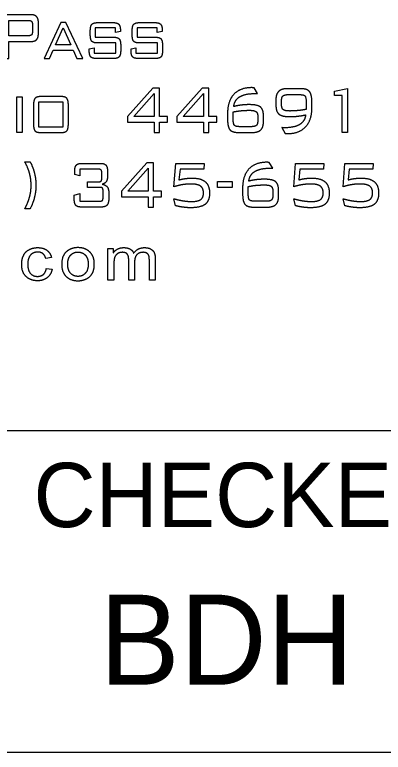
# Model space of a CAD drawing. Extents: x 0 to 34, y 0 to 22.
# Drawn here: x 32.806 to 33.379, y 2.5 to 3.647 of the extents above; entities that cross this region are included whole.
import ezdxf

# ---------------------------------------------------------------- set-up
doc = ezdxf.new("R2010")
doc.units = 0
for name, color, linetype in [('SH_Border', 7, 'Continuous'), ('SH_Data', 7, 'Continuous'), ('TX_X_20', 7, 'Continuous')]:
    doc.layers.add(name, color=color, linetype=linetype)

msp = doc.modelspace()

# ---------------------------------------------------------------- linework, layer by layer
at = {"layer": 'SH_Border'}
for p, q in [((32, 3), (33.5, 3)), ((32, 2.5), (33.5, 2.5))]:
    msp.add_line(p, q, dxfattribs=at)
at = {"layer": 'TX_X_20'}
for p, q in [((32.8336, 3.6306), (32.8336, 3.6211)), ((32.8429, 3.6181), (32.8429, 3.6334)), ((32.9344, 3.6343), (32.9593, 3.6343)), ((32.9994, 3.6343), (33.0243, 3.6343)), ((32.9235, 3.6158), (32.9235, 3.6211)), ((32.9886, 3.6158), (32.9886, 3.6211)), ((32.9708, 3.5984), (32.9708, 3.5917)), ((33.0358, 3.5984), (33.0358, 3.5917)), ((32.9599, 3.5785), (32.9327, 3.5785)), ((33.025, 3.5785), (32.9977, 3.5785)), ((33.1837, 3.524), (33.1782, 3.5329)), ((33.2512, 3.5315), (33.2296, 3.5315)), ((33.2314, 3.5224), (33.248, 3.5224)), ((32.8784, 3.5193), (32.8461, 3.5193)), ((33.2121, 3.5149), (33.2121, 3.5057)), ((33.2208, 3.5075), (33.2208, 3.5119)), ((33.268, 3.5016), (33.268, 3.5105)), ((32.8352, 3.506), (32.8352, 3.4767)), ((32.8894, 3.4767), (32.8894, 3.506)), ((33.259, 3.4994), (33.259, 3.4994)), ((33.1369, 3.4934), (33.1369, 3.4844)), ((33.1457, 3.4955), (33.1457, 3.4955)), ((33.184, 3.4874), (33.184, 3.4831)), ((33.1927, 3.48), (33.1927, 3.4892)), ((32.8461, 3.4635), (32.8784, 3.4635)), ((33.1536, 3.4635), (33.1752, 3.4635)), ((33.1734, 3.4725), (33.1569, 3.4725)), ((33.2211, 3.4711), (33.2266, 3.462)), ((32.8215, 3.4181), (32.8299, 3.4181)), ((33.2072, 3.408), (33.2016, 3.4169)), ((32.9109, 3.4155), (32.9386, 3.4155)), ((32.9415, 3.3947), (32.9415, 3.3987)), ((32.9503, 3.4022), (32.9503, 3.396)), ((32.9434, 3.3629), (32.9434, 3.372)), ((33.1603, 3.3774), (33.1603, 3.3684)), ((33.1692, 3.3795), (33.1692, 3.3795)), ((33.2074, 3.3715), (33.2074, 3.3671)), ((33.2162, 3.364), (33.2162, 3.3733)), ((32.9523, 3.3692), (32.9523, 3.362)), ((33.0561, 3.3496), (33.0535, 3.3605)), ((33.2423, 3.3496), (33.2397, 3.3605)), ((33.3191, 3.3496), (33.3165, 3.3605)), ((33.1969, 3.3565), (33.1803, 3.3565)), ((32.8299, 3.3448), (32.8215, 3.3448)), ((32.9399, 3.3475), (32.9102, 3.3475)), ((33.1771, 3.3475), (33.1987, 3.3475)), ((32.8632, 3.2689), (32.8543, 3.2676)), ((32.879, 3.2587), (32.879, 3.2587)), ((32.8884, 3.2587), (32.8884, 3.2587)), ((32.8551, 3.2521), (32.8641, 3.251))]:
    msp.add_line(p, q, dxfattribs=at)
for points in [[(32.8313, 3.6465), (32.7875, 3.6465), (32.7875, 3.5785), (32.7966, 3.5785), (32.7966, 3.605), (32.8313, 3.605)], [(32.8278, 3.6139), (32.7966, 3.6139), (32.7966, 3.6377), (32.8278, 3.6377)], [(32.9703, 3.6221), (32.9703, 3.6207), (32.9626, 3.6187), (32.9626, 3.626), (32.9312, 3.626), (32.9312, 3.6116), (32.9599, 3.6116)], [(33.0353, 3.6221), (33.0353, 3.6207), (33.0276, 3.6187), (33.0276, 3.626), (32.9963, 3.626), (32.9963, 3.6116), (33.025, 3.6116)], [(32.9218, 3.5917), (32.9218, 3.5933), (32.9295, 3.5953), (32.9295, 3.587), (32.9632, 3.587), (32.9632, 3.6027), (32.9344, 3.6027)], [(32.9868, 3.5917), (32.9868, 3.5933), (32.9945, 3.5953), (32.9945, 3.587), (33.0282, 3.587), (33.0282, 3.6027), (32.9994, 3.6027)], [(32.9366, 3.4064), (32.9074, 3.4064), (32.9074, 3.3959), (32.8992, 3.398), (32.8992, 3.4022)], [(33.0536, 3.3792), (33.0565, 3.4155), (33.1005, 3.4155), (33.0999, 3.4064), (33.0633, 3.4064), (33.0614, 3.3898)], [(33.2398, 3.3792), (33.2426, 3.4155), (33.2867, 3.4155), (33.2861, 3.4064), (33.2495, 3.4064), (33.2476, 3.3898)], [(33.3166, 3.3792), (33.3194, 3.4155), (33.3634, 3.4155), (33.3628, 3.4064), (33.3262, 3.4064), (33.3243, 3.3898)], [(32.9386, 3.3782), (32.9193, 3.3782), (32.9193, 3.3868), (32.9366, 3.3868)], [(32.8985, 3.3608), (32.8985, 3.3663), (32.9072, 3.3688), (32.9072, 3.3568), (32.9386, 3.3568)], [(32.9602, 3.2596), (32.9602, 3.2341), (32.951, 3.2341), (32.951, 3.2834), (32.9592, 3.2834), (32.9592, 3.2764)], [(33.0245, 3.2679), (33.0245, 3.2341), (33.0153, 3.2341), (33.0153, 3.2651)], [(32.9924, 3.2627), (32.9924, 3.2341), (32.9832, 3.2341), (32.9832, 3.2661)]]:
    msp.add_lwpolyline(points, dxfattribs=at)
for points in [[(32.8519, 3.5785), (32.8603, 3.5785), (32.866, 3.5916), (32.8969, 3.5916), (32.9027, 3.5785), (32.9119, 3.5785), (32.8854, 3.6343), (32.8777, 3.6343)], [(32.8696, 3.5996), (32.8814, 3.6262), (32.8933, 3.5996)], [(33.0226, 3.4635), (33.0309, 3.4635), (33.0309, 3.4797), (33.0433, 3.4797), (33.0433, 3.4881), (33.0309, 3.4881), (33.0309, 3.5322), (33.0206, 3.5322), (32.9814, 3.4881), (32.9814, 3.4797), (33.0226, 3.4797)], [(33.0993, 3.4635), (33.1076, 3.4635), (33.1076, 3.4797), (33.1201, 3.4797), (33.1201, 3.4881), (33.1076, 3.4881), (33.1076, 3.5322), (33.0973, 3.5322), (33.0581, 3.4881), (33.0581, 3.4797), (33.0993, 3.4797)], [(33.3152, 3.4635), (33.3152, 3.5208), (33.3033, 3.5208), (33.3033, 3.5276), (33.3235, 3.532), (33.3235, 3.4635)], [(33.0226, 3.4881), (32.991, 3.4881), (33.0226, 3.5241)], [(33.0993, 3.4881), (33.0677, 3.4881), (33.0993, 3.5241)], [(32.8178, 3.4635), (32.8095, 3.4635), (32.8095, 3.5191), (32.8178, 3.5191)], [(32.8436, 3.4719), (32.8436, 3.511), (32.881, 3.511), (32.881, 3.4719)], [(33.0133, 3.3475), (33.0216, 3.3475), (33.0216, 3.3637), (33.0341, 3.3637), (33.0341, 3.3721), (33.0216, 3.3721), (33.0216, 3.4162), (33.0114, 3.4162), (32.9722, 3.3721), (32.9722, 3.3637), (33.0133, 3.3637)], [(33.0133, 3.3721), (32.9817, 3.3721), (33.0133, 3.4081)], [(33.1213, 3.3778), (33.1213, 3.3874), (33.1443, 3.3874), (33.1443, 3.3778)]]:
    msp.add_lwpolyline(points, close=True, dxfattribs=at)
for points in [[(32.8402, 3.6434), (32.8374, 3.6465), (32.8313, 3.6465)], [(32.8278, 3.6377), (32.8311, 3.6377), (32.8324, 3.6361)], [(32.8324, 3.6361), (32.8336, 3.6345), (32.8336, 3.6306)], [(32.8429, 3.6334), (32.8429, 3.6403), (32.8402, 3.6434)], [(32.9235, 3.6211), (32.9235, 3.6287), (32.9258, 3.6315)], [(32.9258, 3.6315), (32.9281, 3.6343), (32.9344, 3.6343)], [(32.9593, 3.6343), (32.9655, 3.6343), (32.9679, 3.6316)], [(32.9679, 3.6316), (32.9703, 3.6289), (32.9703, 3.6221)], [(32.9886, 3.6211), (32.9886, 3.6287), (32.9908, 3.6315)], [(32.9908, 3.6315), (32.9931, 3.6343), (32.9994, 3.6343)], [(33.0243, 3.6343), (33.0306, 3.6343), (33.033, 3.6316)], [(33.033, 3.6316), (33.0353, 3.6289), (33.0353, 3.6221)], [(32.8324, 3.6155), (32.8311, 3.6139), (32.8278, 3.6139)], [(32.8336, 3.6211), (32.8336, 3.6172), (32.8324, 3.6155)], [(32.8402, 3.6081), (32.8429, 3.6112), (32.8429, 3.6181)], [(32.9258, 3.6054), (32.9235, 3.6081), (32.9235, 3.6158)], [(32.9908, 3.6054), (32.9886, 3.6081), (32.9886, 3.6158)], [(32.8313, 3.605), (32.8374, 3.605), (32.8402, 3.6081)], [(32.9344, 3.6027), (32.9281, 3.6027), (32.9258, 3.6054)], [(32.9599, 3.6116), (32.9662, 3.6116), (32.9685, 3.6089)], [(32.9685, 3.6089), (32.9708, 3.6061), (32.9708, 3.5984)], [(32.9994, 3.6027), (32.9931, 3.6027), (32.9908, 3.6054)], [(33.025, 3.6116), (33.0312, 3.6116), (33.0335, 3.6089)], [(33.0335, 3.6089), (33.0358, 3.6061), (33.0358, 3.5984)], [(32.924, 3.5813), (32.9218, 3.584), (32.9218, 3.5917)], [(32.9708, 3.5917), (32.9708, 3.584), (32.9685, 3.5813)], [(32.9891, 3.5813), (32.9868, 3.584), (32.9868, 3.5917)], [(33.0358, 3.5917), (33.0358, 3.584), (33.0336, 3.5813)], [(32.9327, 3.5785), (32.9263, 3.5785), (32.924, 3.5813)], [(32.9685, 3.5813), (32.9663, 3.5785), (32.9599, 3.5785)], [(32.9977, 3.5785), (32.9914, 3.5785), (32.9891, 3.5813)], [(33.0336, 3.5813), (33.0313, 3.5785), (33.025, 3.5785)], [(33.1745, 3.5332), (33.1565, 3.5332), (33.1467, 3.5228)], [(33.176, 3.5331), (33.1752, 3.5332), (33.1745, 3.5332)], [(33.1782, 3.5329), (33.1768, 3.5331), (33.176, 3.5331)], [(33.2296, 3.5315), (33.2206, 3.5315), (33.2164, 3.5274)], [(33.2644, 3.527), (33.2608, 3.5315), (33.2512, 3.5315)], [(33.1467, 3.5228), (33.1369, 3.5124), (33.1369, 3.4934)], [(33.156, 3.5191), (33.1644, 3.5241), (33.1804, 3.5241)], [(33.1804, 3.5241), (33.1817, 3.5241), (33.1824, 3.5241)], [(33.1824, 3.5241), (33.1832, 3.524), (33.1837, 3.524)], [(33.2164, 3.5274), (33.2121, 3.5234), (33.2121, 3.5149)], [(33.2208, 3.5119), (33.2208, 3.518), (33.2229, 3.5202)], [(33.2229, 3.5202), (33.2251, 3.5224), (33.2314, 3.5224)], [(33.248, 3.5224), (33.2559, 3.5224), (33.2576, 3.5199)], [(33.2576, 3.5199), (33.2593, 3.5174), (33.2593, 3.5037)], [(33.268, 3.5105), (33.268, 3.5225), (33.2644, 3.527)], [(32.8375, 3.5165), (32.8352, 3.5137), (32.8352, 3.506)], [(32.8461, 3.5193), (32.8398, 3.5193), (32.8375, 3.5165)], [(32.8871, 3.5165), (32.8848, 3.5193), (32.8784, 3.5193)], [(32.8894, 3.506), (32.8894, 3.5137), (32.8871, 3.5165)], [(33.1465, 3.5039), (33.1477, 3.5142), (33.156, 3.5191)], [(33.1457, 3.4955), (33.1514, 3.4967), (33.1578, 3.4974)], [(33.1584, 3.5061), (33.1524, 3.5053), (33.1465, 3.5039)], [(33.1578, 3.4974), (33.1642, 3.498), (33.1711, 3.498)], [(33.1707, 3.5068), (33.1645, 3.5068), (33.1584, 3.5061)], [(33.1881, 3.503), (33.1834, 3.5068), (33.1707, 3.5068)], [(33.1711, 3.498), (33.1786, 3.498), (33.1813, 3.4958)], [(33.1927, 3.4892), (33.1927, 3.4991), (33.1881, 3.503)], [(33.2121, 3.5057), (33.2121, 3.4959), (33.2168, 3.492)], [(33.2234, 3.4991), (33.2208, 3.5013), (33.2208, 3.5075)], [(33.2336, 3.4969), (33.2261, 3.4969), (33.2234, 3.4991)], [(33.2469, 3.4976), (33.2405, 3.4969), (33.2336, 3.4969)], [(33.259, 3.4994), (33.2533, 3.4982), (33.2469, 3.4976)], [(33.2582, 3.4722), (33.268, 3.4826), (33.268, 3.5016)], [(33.2593, 3.5018), (33.2592, 3.5007), (33.259, 3.4994)], [(33.2593, 3.5037), (33.2593, 3.5029), (33.2593, 3.5018)], [(33.1454, 3.4914), (33.1454, 3.4921), (33.1455, 3.4932)], [(33.1471, 3.4751), (33.1454, 3.4777), (33.1454, 3.4914)], [(33.1455, 3.4932), (33.1456, 3.4942), (33.1457, 3.4955)], [(33.1813, 3.4958), (33.184, 3.4936), (33.184, 3.4874)], [(33.2168, 3.492), (33.2215, 3.4881), (33.2341, 3.4881)], [(33.2341, 3.4881), (33.2403, 3.4881), (33.2464, 3.4889)], [(33.2464, 3.4889), (33.2524, 3.4896), (33.2583, 3.491)], [(33.2583, 3.491), (33.2571, 3.4808), (33.2488, 3.4758)], [(32.8352, 3.4767), (32.8352, 3.4689), (32.8374, 3.4662)], [(32.8871, 3.4662), (32.8894, 3.469), (32.8894, 3.4767)], [(33.1369, 3.4844), (33.1369, 3.4724), (33.1404, 3.4679)], [(33.1569, 3.4725), (33.1489, 3.4725), (33.1471, 3.4751)], [(33.1819, 3.4747), (33.1797, 3.4725), (33.1734, 3.4725)], [(33.184, 3.4831), (33.184, 3.4769), (33.1819, 3.4747)], [(33.1885, 3.4675), (33.1927, 3.4715), (33.1927, 3.48)], [(33.2488, 3.4758), (33.2404, 3.4708), (33.2243, 3.4708)], [(32.8374, 3.4662), (32.8397, 3.4635), (32.8461, 3.4635)], [(32.8784, 3.4635), (32.8848, 3.4635), (32.8871, 3.4662)], [(33.1404, 3.4679), (33.144, 3.4635), (33.1536, 3.4635)], [(33.1752, 3.4635), (33.1842, 3.4635), (33.1885, 3.4675)], [(33.2216, 3.471), (33.2213, 3.471), (33.2211, 3.4711)], [(33.2243, 3.4708), (33.2235, 3.4708), (33.2216, 3.471)], [(33.2303, 3.4618), (33.2483, 3.4618), (33.2582, 3.4722)], [(33.2266, 3.462), (33.2273, 3.4619), (33.228, 3.4619)], [(33.228, 3.4619), (33.2288, 3.4618), (33.2303, 3.4618)], [(32.829, 3.4001), (32.8266, 3.4091), (32.8215, 3.4181)], [(32.8299, 3.4181), (32.8345, 3.4093), (32.8367, 3.4001)], [(33.198, 3.4172), (33.18, 3.4172), (33.1702, 3.4068)], [(33.1995, 3.4171), (33.1987, 3.4172), (33.198, 3.4172)], [(33.2016, 3.4169), (33.2003, 3.4171), (33.1995, 3.4171)], [(32.8992, 3.4022), (32.8992, 3.4098), (32.9016, 3.4127)], [(32.9016, 3.4127), (32.904, 3.4155), (32.9109, 3.4155)], [(32.9405, 3.4049), (32.9395, 3.4064), (32.9366, 3.4064)], [(32.9386, 3.4155), (32.9455, 3.4155), (32.9479, 3.4127)], [(32.9479, 3.4127), (32.9503, 3.4098), (32.9503, 3.4022)], [(33.1702, 3.4068), (33.1603, 3.3964), (33.1603, 3.3774)], [(33.1795, 3.4031), (33.1878, 3.4081), (33.2038, 3.4081)], [(33.2038, 3.4081), (33.2051, 3.4081), (33.2059, 3.4081)], [(33.2059, 3.4081), (33.2066, 3.408), (33.2072, 3.408)], [(32.8315, 3.3814), (32.8315, 3.3912), (32.829, 3.4001)], [(32.8367, 3.4001), (32.839, 3.391), (32.839, 3.3814)], [(32.9415, 3.3987), (32.9415, 3.4034), (32.9405, 3.4049)], [(32.9405, 3.3883), (32.9415, 3.3898), (32.9415, 3.3947)], [(32.9503, 3.396), (32.9503, 3.3902), (32.9484, 3.3873)], [(33.17, 3.3879), (33.1712, 3.3982), (33.1795, 3.4031)], [(32.9366, 3.3868), (32.9395, 3.3868), (32.9405, 3.3883)], [(32.9484, 3.3873), (32.9465, 3.3843), (32.9421, 3.3831)], [(32.9421, 3.3831), (32.9475, 3.382), (32.9499, 3.3788)], [(33.0676, 3.3824), (33.061, 3.3814), (33.0536, 3.3792)], [(33.0614, 3.3898), (33.0665, 3.3913), (33.0715, 3.3919)], [(33.0804, 3.3834), (33.0743, 3.3834), (33.0676, 3.3824)], [(33.0715, 3.3919), (33.0765, 3.3926), (33.0816, 3.3926)], [(33.0949, 3.3801), (33.0904, 3.3834), (33.0804, 3.3834)], [(33.0816, 3.3926), (33.0955, 3.3926), (33.1022, 3.3869)], [(33.1022, 3.3869), (33.1089, 3.3812), (33.1089, 3.3693)], [(33.1819, 3.3901), (33.1759, 3.3893), (33.17, 3.3879)], [(33.1942, 3.3908), (33.1879, 3.3908), (33.1819, 3.3901)], [(33.2115, 3.387), (33.2068, 3.3908), (33.1942, 3.3908)], [(33.2162, 3.3733), (33.2162, 3.3832), (33.2115, 3.387)], [(33.2538, 3.3824), (33.2472, 3.3814), (33.2398, 3.3792)], [(33.2476, 3.3898), (33.2527, 3.3913), (33.2577, 3.3919)], [(33.2666, 3.3834), (33.2604, 3.3834), (33.2538, 3.3824)], [(33.2577, 3.3919), (33.2627, 3.3926), (33.2678, 3.3926)], [(33.2811, 3.3801), (33.2766, 3.3834), (33.2666, 3.3834)], [(33.2678, 3.3926), (33.2817, 3.3926), (33.2883, 3.3869)], [(33.2883, 3.3869), (33.295, 3.3812), (33.295, 3.3693)], [(33.3306, 3.3824), (33.3239, 3.3814), (33.3166, 3.3792)], [(33.3243, 3.3898), (33.3294, 3.3913), (33.3344, 3.3919)], [(33.3433, 3.3834), (33.3372, 3.3834), (33.3306, 3.3824)], [(33.3344, 3.3919), (33.3395, 3.3926), (33.3445, 3.3926)], [(33.3579, 3.3801), (33.3533, 3.3834), (33.3433, 3.3834)], [(33.3445, 3.3926), (33.3584, 3.3926), (33.3651, 3.3869)], [(33.3651, 3.3869), (33.3718, 3.3812), (33.3718, 3.3693)], [(32.829, 3.3628), (32.8315, 3.3719), (32.8315, 3.3814)], [(32.839, 3.3814), (32.839, 3.372), (32.8367, 3.3628)], [(32.9425, 3.377), (32.9415, 3.3782), (32.9386, 3.3782)], [(32.9434, 3.372), (32.9434, 3.3758), (32.9425, 3.377)], [(32.9499, 3.3788), (32.9523, 3.3755), (32.9523, 3.3692)], [(33.0995, 3.3695), (33.0995, 3.3768), (33.0949, 3.3801)], [(33.1688, 3.3754), (33.1688, 3.3762), (33.1689, 3.3772)], [(33.1706, 3.3591), (33.1688, 3.3617), (33.1688, 3.3754)], [(33.1689, 3.3772), (33.169, 3.3782), (33.1692, 3.3795)], [(33.1692, 3.3795), (33.1749, 3.3807), (33.1813, 3.3814)], [(33.1813, 3.3814), (33.1877, 3.382), (33.1946, 3.382)], [(33.1946, 3.382), (33.2021, 3.382), (33.2048, 3.3798)], [(33.2048, 3.3798), (33.2074, 3.3776), (33.2074, 3.3715)], [(33.2856, 3.3695), (33.2856, 3.3768), (33.2811, 3.3801)], [(33.3624, 3.3695), (33.3624, 3.3768), (33.3579, 3.3801)], [(32.8215, 3.3448), (32.8265, 3.3536), (32.829, 3.3628)], [(32.8367, 3.3628), (32.8345, 3.3537), (32.8299, 3.3448)], [(32.9009, 3.3503), (32.8985, 3.3531), (32.8985, 3.3608)], [(32.9425, 3.358), (32.9434, 3.3592), (32.9434, 3.3629)], [(32.9523, 3.362), (32.9523, 3.3537), (32.9495, 3.3506)], [(33.0535, 3.3605), (33.0609, 3.3584), (33.0679, 3.3573)], [(33.0952, 3.3593), (33.0995, 3.3624), (33.0995, 3.3695)], [(33.1089, 3.3693), (33.1089, 3.3572), (33.102, 3.3518)], [(33.1603, 3.3684), (33.1603, 3.3564), (33.1639, 3.3519)], [(33.2074, 3.3671), (33.2074, 3.3609), (33.2053, 3.3587)], [(33.212, 3.3515), (33.2162, 3.3555), (33.2162, 3.364)], [(33.2397, 3.3605), (33.2471, 3.3584), (33.2541, 3.3573)], [(33.2814, 3.3593), (33.2856, 3.3624), (33.2856, 3.3695)], [(33.295, 3.3693), (33.295, 3.3572), (33.2882, 3.3518)], [(33.3165, 3.3605), (33.3239, 3.3584), (33.3309, 3.3573)], [(33.3581, 3.3593), (33.3624, 3.3624), (33.3624, 3.3695)], [(33.3718, 3.3693), (33.3718, 3.3572), (33.3649, 3.3518)], [(32.9102, 3.3475), (32.9033, 3.3475), (32.9009, 3.3503)], [(32.9386, 3.3568), (32.9415, 3.3568), (32.9425, 3.358)], [(32.9495, 3.3506), (32.9468, 3.3475), (32.9399, 3.3475)], [(33.0689, 3.3472), (33.0633, 3.3479), (33.0561, 3.3496)], [(33.0679, 3.3573), (33.0749, 3.3562), (33.081, 3.3562)], [(33.102, 3.3518), (33.0952, 3.3465), (33.0795, 3.3465)], [(33.081, 3.3562), (33.0909, 3.3562), (33.0952, 3.3593)], [(33.1639, 3.3519), (33.1674, 3.3475), (33.1771, 3.3475)], [(33.1803, 3.3565), (33.1724, 3.3565), (33.1706, 3.3591)], [(33.2053, 3.3587), (33.2032, 3.3565), (33.1969, 3.3565)], [(33.1987, 3.3475), (33.2077, 3.3475), (33.212, 3.3515)], [(33.255, 3.3472), (33.2495, 3.3479), (33.2423, 3.3496)], [(33.2541, 3.3573), (33.2611, 3.3562), (33.2672, 3.3562)], [(33.2882, 3.3518), (33.2813, 3.3465), (33.2656, 3.3465)], [(33.2672, 3.3562), (33.2771, 3.3562), (33.2814, 3.3593)], [(33.3318, 3.3472), (33.3262, 3.3479), (33.3191, 3.3496)], [(33.3309, 3.3573), (33.3379, 3.3562), (33.3439, 3.3562)], [(33.3649, 3.3518), (33.3581, 3.3465), (33.3424, 3.3465)], [(33.3439, 3.3562), (33.3538, 3.3562), (33.3581, 3.3593)], [(33.0795, 3.3465), (33.0744, 3.3465), (33.0689, 3.3472)], [(33.2656, 3.3465), (33.2606, 3.3465), (33.255, 3.3472)], [(33.3424, 3.3465), (33.3374, 3.3465), (33.3318, 3.3472)], [(32.8198, 3.2725), (32.8227, 3.2785), (32.8286, 3.2815)], [(32.8286, 3.2815), (32.8346, 3.2845), (32.8416, 3.2845)], [(32.8416, 3.2845), (32.8504, 3.2845), (32.856, 3.2804)], [(32.856, 3.2804), (32.8616, 3.2763), (32.8632, 3.2689)], [(32.9044, 3.2845), (32.8943, 3.2845), (32.8873, 3.279)], [(32.9227, 3.2778), (32.9156, 3.2845), (32.9044, 3.2845)], [(32.9592, 3.2764), (32.9617, 3.2801), (32.966, 3.2823)], [(32.966, 3.2823), (32.9702, 3.2845), (32.9756, 3.2845)], [(32.9756, 3.2845), (32.9817, 3.2845), (32.9855, 3.2822)], [(32.9855, 3.2822), (32.9894, 3.2799), (32.991, 3.2758)], [(32.991, 3.2758), (32.9974, 3.2845), (33.0077, 3.2845)], [(33.0077, 3.2845), (33.0158, 3.2845), (33.0201, 3.2804)], [(33.0201, 3.2804), (33.0245, 3.2764), (33.0245, 3.2679)], [(32.8168, 3.2585), (32.8168, 3.2665), (32.8198, 3.2725)], [(32.8307, 3.2731), (32.8263, 3.2686), (32.8263, 3.2588)], [(32.8419, 3.2776), (32.835, 3.2776), (32.8307, 3.2731)], [(32.8498, 3.2751), (32.8465, 3.2776), (32.8419, 3.2776)], [(32.8543, 3.2676), (32.853, 3.2726), (32.8498, 3.2751)], [(32.8873, 3.279), (32.879, 3.2724), (32.879, 3.2587)], [(32.8884, 3.2587), (32.8884, 3.2682), (32.893, 3.2729)], [(32.893, 3.2729), (32.8975, 3.2776), (32.9044, 3.2776)], [(32.9044, 3.2776), (32.9112, 3.2776), (32.9157, 3.2729)], [(32.9157, 3.2729), (32.9203, 3.2682), (32.9203, 3.259)], [(32.9297, 3.2594), (32.9297, 3.2712), (32.9227, 3.2778)], [(32.9616, 3.2699), (32.9602, 3.2664), (32.9602, 3.2596)], [(32.9664, 3.2754), (32.9631, 3.2735), (32.9616, 3.2699)], [(32.9736, 3.2772), (32.9697, 3.2772), (32.9664, 3.2754)], [(32.9809, 3.2744), (32.9787, 3.2772), (32.9736, 3.2772)], [(32.9832, 3.2661), (32.9832, 3.2717), (32.9809, 3.2744)], [(32.9962, 3.2738), (32.9924, 3.2703), (32.9924, 3.2627)], [(33.0057, 3.2772), (32.9999, 3.2772), (32.9962, 3.2738)], [(33.0112, 3.2759), (33.0088, 3.2772), (33.0057, 3.2772)], [(33.0144, 3.2723), (33.0135, 3.2745), (33.0112, 3.2759)], [(33.0153, 3.2651), (33.0153, 3.2701), (33.0144, 3.2723)], [(32.8236, 3.2396), (32.8168, 3.2462), (32.8168, 3.2585)], [(32.8263, 3.2588), (32.8263, 3.2488), (32.8305, 3.2443)], [(32.879, 3.2587), (32.879, 3.2463), (32.886, 3.2396)], [(32.893, 3.2445), (32.8884, 3.2493), (32.8884, 3.2587)], [(32.9203, 3.259), (32.9203, 3.2493), (32.9157, 3.2446)], [(32.9266, 3.2445), (32.9297, 3.2499), (32.9297, 3.2594)], [(32.8505, 3.2428), (32.8541, 3.2459), (32.8551, 3.2521)], [(32.8641, 3.251), (32.8626, 3.2426), (32.8565, 3.2378)], [(32.8415, 3.233), (32.8304, 3.233), (32.8236, 3.2396)], [(32.8305, 3.2443), (32.8347, 3.2398), (32.8414, 3.2398)], [(32.8414, 3.2398), (32.8468, 3.2398), (32.8505, 3.2428)], [(32.8565, 3.2378), (32.8504, 3.233), (32.8415, 3.233)], [(32.886, 3.2396), (32.893, 3.233), (32.9044, 3.233)], [(32.9044, 3.2398), (32.8975, 3.2398), (32.893, 3.2445)], [(32.9157, 3.2446), (32.9112, 3.2398), (32.9044, 3.2398)], [(32.9044, 3.233), (32.9115, 3.233), (32.9175, 3.236)], [(32.9175, 3.236), (32.9235, 3.239), (32.9266, 3.2445)]]:
    msp.add_open_spline(points, degree=2, dxfattribs=at)

# ---------------------------------------------------------------- texts
at = {"layer": 'SH_Data'}
for s, height, p in [('CHECKER', 0.1, (32.8352, 2.85)), ('BDH', 0.14, (32.9377, 2.605))]:
    msp.add_text(s, height=height, dxfattribs=at).set_placement(p)

doc.saveas('drawing.dxf')
